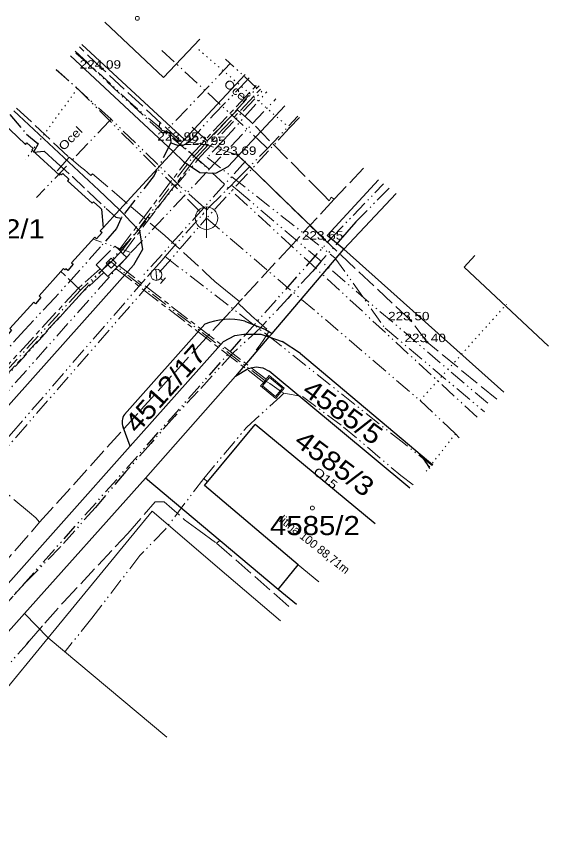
# Model space of a CAD drawing. Extents: x -683947 to -683762, y -1065756 to -1065543.
# Drawn here: x -683809.8 to -683762.4, y -1065615.3 to -1065542.6 of the extents above; entities that cross this region are included whole.
import ezdxf
from ezdxf.enums import TextEntityAlignment as Align

# ---------------------------------------------------------------- set-up
doc = ezdxf.new("R2010")
doc.units = 0
doc.header["$LTSCALE"] = 0.3
doc.header["$PDMODE"] = 32
doc.header["$PDSIZE"] = 0.15
for name, pattern in [('DASH_DOUBLE_DOT', [9.2, 5, -1.2, 0.3, -1.2, 0.3, -1.2]), ('DOTTED', [1.5, 0.3, -1.2]), ('LONG_DASH_SHORT_DASH', [9.9, 6, -1.2, 1.5, -1.2]), ('LONG_DASHED', [7.5, 6, -1.5])]:
    doc.linetypes.add(name, pattern=pattern)
for name, color, linetype, lineweight in [('1', 7, 'Continuous', 25), ('10', 7, 'Continuous', 13), ('25', 7, 'Continuous', 13), ('26', 7, 'LONG_DASH_SHORT_DASH', 13), ('3', 7, 'Continuous', 13), ('30', 7, 'LONG_DASHED', 13), ('31', 7, 'DASH_DOUBLE_DOT', 13), ('35', 7, 'LONG_DASHED', 13), ('36', 7, 'DASH_DOUBLE_DOT', 25), ('4', 7, 'Continuous', 13), ('41', 7, 'DASH_DOUBLE_DOT', 13), ('46', 7, 'DASH_DOUBLE_DOT', 13), ('5', 7, 'Continuous', 13), ('50', 7, 'LONG_DASHED', 13), ('51', 7, 'DOTTED', 13)]:
    doc.layers.add(name, color=color, linetype=linetype, lineweight=lineweight)
for name, color, linetype in [('16', 7, 'Continuous'), ('19', 7, 'Continuous'), ('2', 7, 'Continuous')]:
    doc.layers.add(name, color=color, linetype=linetype)

msp = doc.modelspace()

# ---------------------------------------------------------------- linework, layer by layer
at = {"layer": '1'}
for p, q in [((-683796.73, -1065548.04), (-683801.928, -1065543.107)), ((-683793.476, -1065544.62), (-683796.73, -1065548.04)), ((-683803.987, -1065545.115), (-683794.86, -1065553.55)), ((-683794.86, -1065553.55), (-683789.456, -1065547.788)), ((-683785.932, -1065550.565), (-683790.97, -1065555.96)), ((-683811.072, -1065552.024), (-683809.01, -1065554)), ((-683795.86, -1065554.64), (-683794.86, -1065553.55)), ((-683782.15, -1065562.09), (-683777.576, -1065557.148)), ((-683780.67, -1065563.32), (-683776.02, -1065558.374)), ((-683800.63, -1065559.83), (-683800.25, -1065560.2)), ((-683802.83, -1065562.26), (-683804.91, -1065564.54)), ((-683802.67, -1065562.4), (-683802.83, -1065562.26)), ((-683780.67, -1065563.32), (-683782.15, -1065562.09)), ((-683787.06, -1065570.81), (-683780.67, -1065563.32)), ((-683766.438, -1065576.048), (-683780.67, -1065563.32)), ((-683769.97, -1065564.92), (-683769.021, -1065563.888)), ((-683799.39, -1065564.75), (-683850.61, -1065622.17)), ((-683805.49, -1065565.16), (-683805.61, -1065565.05)), ((-683805.41, -1065565.07), (-683805.49, -1065565.16)), ((-683805.23, -1065565.23), (-683805.41, -1065565.07)), ((-683762.438, -1065571.952), (-683769.97, -1065564.92)), ((-683793.05, -1065570), (-683800.2, -1065578.03)), ((-683789.48, -1065569.72), (-683787.65, -1065570.48)), ((-683790.37, -1065571.01), (-683789.58, -1065570.87)), ((-683789.58, -1065570.87), (-683788.05, -1065570.87)), ((-683788.05, -1065570.87), (-683787.33, -1065571.13)), ((-683787.65, -1065570.48), (-683787.06, -1065570.81)), ((-683787.33, -1065571.13), (-683787.06, -1065570.81)), ((-683799.69, -1065580.85), (-683791.39, -1065571.52)), ((-683791.39, -1065571.52), (-683790.37, -1065571.01)), ((-683787.33, -1065571.13), (-683790.32, -1065574.63)), ((-683787.33, -1065571.13), (-683786.17, -1065571.54)), ((-683784.52, -1065572.61), (-683786.17, -1065571.54)), ((-683784.52, -1065572.61), (-683774.26, -1065581.22)), ((-683789.19, -1065573.93), (-683788.48, -1065573.79)), ((-683788.48, -1065573.79), (-683787.87, -1065573.87)), ((-683787.87, -1065573.87), (-683787.3, -1065574.18)), ((-683790.32, -1065574.63), (-683789.19, -1065573.93)), ((-683774.788, -1065584.598), (-683787.3, -1065574.18)), ((-683798.31, -1065583.7), (-683790.32, -1065574.63)), ((-683793.07, -1065584.35), (-683788.55, -1065578.91)), ((-683777.88, -1065587.764), (-683788.55, -1065578.91)), ((-683799.69, -1065580.85), (-683800.32, -1065579.15)), ((-683844.35, -1065631.04), (-683799.69, -1065580.85)), ((-683774.26, -1065581.22), (-683772.74, -1065582.501)), ((-683798.31, -1065583.7), (-683809.1, -1065595.75)), ((-683786.5, -1065593.59), (-683798.31, -1065583.7)), ((-683784.73, -1065591.4), (-683793.07, -1065584.35)), ((-683786.5, -1065593.59), (-683784.73, -1065591.4)), ((-683784.888, -1065594.94), (-683786.5, -1065593.59)), ((-683809.1, -1065595.75), (-683842.21, -1065632.76))]:
    msp.add_line(p, q, dxfattribs=at)
for points in [[(-683809.01, -1065554), (-683808.87, -1065553.86), (-683808.32, -1065554.37), (-683808.43, -1065554.49)], [(-683808.43, -1065554.49), (-683805.98, -1065556.74), (-683805.88, -1065556.63), (-683805.8, -1065556.71), (-683805.68, -1065556.58), (-683805.13, -1065557.09), (-683805.26, -1065557.23), (-683803.07, -1065559.24), (-683802.94, -1065559.1), (-683802.38, -1065559.61), (-683802.24, -1065559.77), (-683802.09, -1065561.42), (-683802.35, -1065561.7), (-683802.18, -1065561.85), (-683802.67, -1065562.4)], [(-683795.86, -1065554.64), (-683800.63, -1065559.83), (-683802.09, -1065561.42)], [(-683795.86, -1065554.64), (-683794.95, -1065555.51), (-683793.49, -1065556.51), (-683792.07, -1065556.55), (-683790.97, -1065555.96)], [(-683800.25, -1065560.2), (-683799.65, -1065560.85), (-683798.86, -1065561.69)], [(-683798.86, -1065561.69), (-683798.6, -1065563.36), (-683799.39, -1065564.75)], [(-683805.61, -1065565.05), (-683807.78, -1065567.47), (-683807.63, -1065567.62), (-683808.11, -1065568.17), (-683808.27, -1065568.02)], [(-683804.91, -1065564.54), (-683804.76, -1065564.66), (-683805.23, -1065565.23)], [(-683808.27, -1065568.02), (-683810.39, -1065570.39), (-683810.24, -1065570.54), (-683810.72, -1065571.09), (-683810.9, -1065570.93)], [(-683774.26, -1065581.22), (-683774.14, -1065581.342), (-683774.023, -1065581.467), (-683773.91, -1065581.595), (-683773.799, -1065581.726), (-683773.692, -1065581.859), (-683773.587, -1065581.995), (-683773.487, -1065582.133), (-683773.389, -1065582.274), (-683773.295, -1065582.416), (-683773.204, -1065582.562), (-683773.117, -1065582.709), (-683773.053, -1065582.822)]]:
    msp.add_lwpolyline(points, dxfattribs=at)
for centre, radius, start, end in [((-683790.831, -1065575.396), 5.835, 76.6146, 112.35461), ((-683799.206, -1065578.703), 1.201, 145.91206, 201.85693)]:
    msp.add_arc(centre, radius, start, end, dxfattribs=at)
for p in [(-683802.17, -1065547.26), (-683794.85, -1065553.57), (-683795.26, -1065553.67), (-683792.85, -1065554.05), (-683790.12, -1065554.93), (-683782.39, -1065562.47), (-683774.72, -1065569.65), (-683773.26, -1065571.59)]:
    msp.add_point(p, dxfattribs=at)
at = {"layer": '10'}
for p, q in [((-683792.885, -1065559.565), (-683792.885, -1065562.313)), ((-683797.393, -1065565.093), (-683797.323, -1065566.091)), ((-683796.524, -1065565.855), (-683796.982, -1065566.383)), ((-683796.98, -1065565.923), (-683796.753, -1065566.12))]:
    msp.add_line(p, q, dxfattribs=at)
for centre, radius in [((-683792.885, -1065560.567), 1), ((-683797.358, -1065565.594), 0.5)]:
    msp.add_circle(centre, radius, dxfattribs=at)
at = {"layer": '25'}
for p, q in [((-683790.099, -1065554.894), (-683790.145, -1065554.94)), ((-683790.095, -1065554.948), (-683782.367, -1065562.451))]:
    msp.add_line(p, q, dxfattribs=at)
at = {"layer": '26'}
for p, q in [((-683800.96, -1065565.04), (-683787.8, -1065575.17)), ((-683800.7, -1065564.78), (-683787.57, -1065574.9))]:
    msp.add_line(p, q, dxfattribs=at)
for points in [[(-683800.67, -1065563.39), (-683794.31, -1065555), (-683788.371, -1065548.643)], [(-683800.35, -1065563.72), (-683793.93, -1065555.32), (-683787.98, -1065548.95)], [(-683802.34, -1065565.06), (-683804.28, -1065566.78), (-683816.53, -1065580.13), (-683823.89, -1065588.24), (-683833.6, -1065599.23)], [(-683802.02, -1065565.39), (-683803.92, -1065567.14), (-683816.16, -1065580.47), (-683823.51, -1065588.58), (-683833.25, -1065599.54)]]:
    msp.add_lwpolyline(points, dxfattribs=at)
for points in [[(-683802.7, -1065564.71), (-683801.03, -1065563.04), (-683800.67, -1065563.39), (-683800.35, -1065563.72), (-683799.99, -1065564.07), (-683800.7, -1065564.78), (-683800.96, -1065565.04), (-683801.66, -1065565.74), (-683802.02, -1065565.39), (-683802.34, -1065565.06)], [(-683801.82, -1065564.57), (-683801.38, -1065564.13), (-683800.94, -1065564.57), (-683801.38, -1065565.01)], [(-683788.07, -1065575.49), (-683787.8, -1065575.17), (-683787.57, -1065574.9), (-683787.3, -1065574.57), (-683785.97, -1065575.69), (-683786.23, -1065576.01), (-683786.47, -1065576.29), (-683786.73, -1065576.61)], [(-683787.9, -1065575.48), (-683787.29, -1065574.74), (-683786.13, -1065575.7), (-683786.75, -1065576.44)]]:
    msp.add_lwpolyline(points, close=True, dxfattribs=at)
at = {"layer": '30'}
for points in [[(-683790.12, -1065554.93), (-683792.85, -1065554.05), (-683795.26, -1065553.67), (-683802.17, -1065547.26), (-683804.196, -1065545.319)], [(-683767.054, -1065576.678), (-683773.26, -1065571.59), (-683774.72, -1065569.65), (-683782.39, -1065562.47), (-683790.12, -1065554.93)]]:
    msp.add_lwpolyline(points, dxfattribs=at)
at = {"layer": '31'}
for p, q in [((-683788.4, -1065548.98), (-683791.191, -1065546.421)), ((-683788.4, -1065548.98), (-683788.205, -1065548.773)), ((-683791.34, -1065553.6), (-683787.516, -1065549.316)), ((-683799.62, -1065563.63), (-683802.97, -1065562.42)), ((-683776.99, -1065570.36), (-683768.144, -1065577.794)), ((-683786, -1065576.14), (-683786.22, -1065576)), ((-683793.13, -1065583.71), (-683792.8, -1065584.01))]:
    msp.add_line(p, q, dxfattribs=at)
for points in [[(-683792.64, -1065556.2), (-683799.41, -1065550.51), (-683804.577, -1065545.69)], [(-683844.16, -1065612.25), (-683839.52, -1065607), (-683832.27, -1065598.52), (-683799.27, -1065561.98), (-683793.42, -1065555.08), (-683787.795, -1065549.096)], [(-683801.38, -1065564.44), (-683800.5, -1065563.57), (-683794.12, -1065555.16), (-683788.4, -1065548.98)], [(-683799.62, -1065563.63), (-683792.64, -1065556.2), (-683786.719, -1065549.944)], [(-683791.34, -1065553.6), (-683792.82, -1065555.16), (-683781.46, -1065564.09), (-683776.99, -1065570.36)], [(-683841.77, -1065605.48), (-683839.42, -1065608.5), (-683799.62, -1065563.63)], [(-683801.38, -1065564.44), (-683804.1, -1065566.96), (-683816.34, -1065580.3), (-683823.7, -1065588.41)], [(-683786.22, -1065576), (-683787.26, -1065575.28), (-683787.68, -1065575.03), (-683800.84, -1065564.91), (-683801.38, -1065564.44)], [(-683804.1, -1065566.96), (-683805.53, -1065565.6), (-683805.84, -1065565.31)], [(-683793.13, -1065583.71), (-683789.3, -1065579.15), (-683786.34, -1065576.47), (-683786, -1065576.14)], [(-683786, -1065576.14), (-683784.35, -1065576.43), (-683780.69, -1065579.15), (-683775.58, -1065583.47), (-683774.482, -1065584.284)], [(-683793.13, -1065583.71), (-683796.54, -1065588.22), (-683798.81, -1065590.57), (-683803.09, -1065596.16), (-683805.48, -1065599.12)]]:
    msp.add_lwpolyline(points, dxfattribs=at)
at = {"layer": '35'}
for p, q in [((-683791.086, -1065558.025), (-683790.672, -1065557.612)), ((-683791.987, -1065589.477), (-683791.739, -1065589.28)), ((-683791.987, -1065589.477), (-683785.281, -1065595.342))]:
    msp.add_line(p, q, dxfattribs=at)
for points in [[(-683809.787, -1065550.771), (-683805.12, -1065555.14), (-683804.1, -1065555.98), (-683803.75, -1065556.26), (-683803.48, -1065556.51)], [(-683778.905, -1065556.101), (-683781.53, -1065558.87), (-683785.235, -1065562.893), (-683789.699, -1065567.708), (-683789.948, -1065567.987), (-683790.074, -1065568.129)], [(-683803.48, -1065556.51), (-683803.19, -1065556.77), (-683803.03, -1065556.62), (-683796.6, -1065562.1), (-683792.978, -1065565.422), (-683792.14, -1065566.19), (-683791.185, -1065566.973), (-683789.948, -1065567.987)], [(-683790.672, -1065557.612), (-683790.402, -1065557.337), (-683790.126, -1065557.059)], [(-683790.672, -1065557.612), (-683790.454, -1065557.792), (-683790.158, -1065558.044)], [(-683896.24, -1065687.55), (-683894.71, -1065685.72), (-683893.48, -1065684.13), (-683891.61, -1065681.955), (-683887.89, -1065677.63), (-683886.16, -1065675.53), (-683853.44, -1065639.1), (-683848.45, -1065633.59), (-683843.114, -1065627.22), (-683843.08, -1065627.18), (-683831.4, -1065614.21), (-683820.06, -1065601.41), (-683812.91, -1065593.55), (-683807.75, -1065587.62), (-683793.84, -1065572.21), (-683791.969, -1065570.179), (-683790.708, -1065568.809), (-683790.074, -1065568.129)], [(-683790.074, -1065568.129), (-683788.87, -1065569.24), (-683787.32, -1065570.62), (-683787.85, -1065571.46), (-683788.04, -1065571.73), (-683788.47, -1065572.31)], [(-683808.67, -1065598.185), (-683807.29, -1065596.593), (-683805.621, -1065594.724), (-683799.904, -1065588.627), (-683797.444, -1065585.805), (-683796.652, -1065585.795)], [(-683796.652, -1065585.795), (-683794.833, -1065587.39), (-683793.539, -1065588.345), (-683791.987, -1065589.477)]]:
    msp.add_lwpolyline(points, dxfattribs=at)
at = {"layer": '36'}
for p, q in [((-683796.15, -1065552.96), (-683796.05, -1065553.86)), ((-683776.644, -1065557.882), (-683779.59, -1065560.9)), ((-683779.59, -1065560.9), (-683780.391, -1065561.807))]:
    msp.add_line(p, q, dxfattribs=at)
at = {"layer": '36', "lineweight": 13}
for p, q in [((-683789.43, -1065555.5), (-683798.629, -1065565.77)), ((-683790.158, -1065558.044), (-683767.603, -1065577.241)), ((-683796.578, -1065563.976), (-683792.872, -1065559.824)), ((-683796.84, -1065564.29), (-683796.578, -1065563.976)), ((-683796.27, -1065564.22), (-683796.578, -1065563.976))]:
    msp.add_line(p, q, dxfattribs=at)
at = {"layer": '36'}
for points in [[(-683796.15, -1065552.96), (-683796.82, -1065552.97), (-683798.58, -1065551.35), (-683800.66, -1065549.45), (-683803.39, -1065546.85), (-683804.656, -1065545.768)], [(-683796.05, -1065553.86), (-683795.46, -1065554.07), (-683794.97, -1065554.08), (-683794.39, -1065553.76), (-683792.25, -1065551.34), (-683789.87, -1065548.91), (-683789.101, -1065548.068)], [(-683810.38, -1065551.349), (-683808.92, -1065553.09), (-683807.88, -1065553.96), (-683808.28, -1065554.7)], [(-683796.15, -1065552.96), (-683796.84, -1065552.77), (-683797.1, -1065552.45), (-683797.01, -1065552.04)], [(-683796.05, -1065553.86), (-683797.56, -1065556.77), (-683800.49, -1065560.55)], [(-683808.28, -1065554.7), (-683807.34, -1065554.61), (-683806.23, -1065555.6), (-683804.83, -1065556.86), (-683803.35, -1065558.25), (-683801.83, -1065559.69), (-683800.97, -1065560.48), (-683800.49, -1065560.55)], [(-683800.49, -1065560.55), (-683800.89, -1065561.47), (-683802.33, -1065563.11), (-683804.19, -1065565.23), (-683806.4, -1065567.64), (-683809.07, -1065570.49), (-683811.9, -1065573.65), (-683813.94, -1065576.12), (-683815.51, -1065577.95)], [(-683780.391, -1065561.807), (-683782.7, -1065564.42), (-683783.44, -1065565.28), (-683785.65, -1065567.7), (-683788.09, -1065570.32), (-683790.52, -1065572.55), (-683793.62, -1065575.94), (-683795.75, -1065578.2), (-683797.85, -1065580.61), (-683800.07, -1065583.11), (-683802.78, -1065586.29), (-683805.93, -1065589.86), (-683808.99, -1065592.97), (-683812.14, -1065596.4), (-683814.68, -1065599.44), (-683817.17, -1065602.3), (-683820.49, -1065605.87), (-683823.62, -1065609.31), (-683825.7, -1065611.73), (-683828.07, -1065614.55), (-683831.17, -1065618.13)], [(-683816.844, -1065611.315), (-683817.806, -1065610.911), (-683818.52, -1065610.227), (-683818.714, -1065609.734), (-683818.377, -1065609.192), (-683817.615, -1065607.976), (-683815.022, -1065605.096), (-683812.85, -1065602.939), (-683811.5, -1065601.448), (-683808.88, -1065598.46), (-683808.67, -1065598.185)]]:
    msp.add_lwpolyline(points, dxfattribs=at)
at = {"layer": '36', "lineweight": 13}
for points in [[(-683795.228, -1065557.729), (-683801.38, -1065551.757), (-683806.265, -1065547.336)], [(-683790.126, -1065557.059), (-683787.448, -1065554.367), (-683784.757, -1065551.49)], [(-683792.872, -1065559.824), (-683793.348, -1065559.395), (-683795.228, -1065557.729)], [(-683792.872, -1065559.824), (-683792.66, -1065559.596), (-683791.086, -1065558.025)], [(-683853.405, -1065628.437), (-683847.424, -1065621.75), (-683837.692, -1065610.319), (-683826.563, -1065598.101), (-683821.765, -1065592.734), (-683810.241, -1065579.722), (-683798.152, -1065565.762), (-683797.335, -1065564.872), (-683796.84, -1065564.29)], [(-683772.814, -1065582.577), (-683775.342, -1065580.59), (-683786.55, -1065571.679), (-683796.27, -1065564.22)]]:
    msp.add_lwpolyline(points, dxfattribs=at)
at = {"layer": '4'}
for p, q in [((-683805.006, -1065546.109), (-683795.86, -1065554.64)), ((-683802.48, -1065558.07), (-683810.031, -1065551.009)), ((-683802.48, -1065558.07), (-683800.63, -1065559.83)), ((-683806.98, -1065597.89), (-683797.73, -1065586.62)), ((-683797.73, -1065586.62), (-683791.1, -1065592.29)), ((-683784.73, -1065591.4), (-683782.9, -1065592.904)), ((-683791.1, -1065592.29), (-683786.304, -1065596.39)), ((-683809.1, -1065595.75), (-683806.98, -1065597.89)), ((-683817.57, -1065610.69), (-683806.98, -1065597.89)), ((-683796.424, -1065606.751), (-683806.98, -1065597.89))]:
    msp.add_line(p, q, dxfattribs=at)
at = {"layer": '41'}
for p, q in [((-683790.74, -1065546.776), (-683796.47, -1065552.759)), ((-683796.47, -1065552.759), (-683768.698, -1065578.362))]:
    msp.add_line(p, q, dxfattribs=at)
at = {"layer": '41', "lineweight": 25}
msp.add_lwpolyline([(-683907.26, -1065705.67), (-683893.37, -1065687.98), (-683887.71, -1065681.96), (-683876.81, -1065669.67), (-683869.01, -1065660.17), (-683861.43, -1065651.54), (-683852.89, -1065642.04), (-683845.02, -1065633.03), (-683836.31, -1065623.45), (-683820.34, -1065605.7), (-683789.54, -1065571.05), (-683781.76, -1065562.31), (-683777.124, -1065557.504)], dxfattribs=at)
at = {"layer": '46'}
for points in [[(-683806.282, -1065547.353), (-683804.37, -1065549.013), (-683792.885, -1065560.567)], [(-683784.617, -1065551.6), (-683785.49, -1065552.529), (-683792.885, -1065560.567)], [(-683826.197, -1065598.918), (-683819.004, -1065590.616), (-683809.84, -1065580.04), (-683792.885, -1065560.567)], [(-683792.885, -1065560.567), (-683773.884, -1065576.785), (-683770.73, -1065579.748), (-683770.391, -1065580.095)]]:
    msp.add_lwpolyline(points, dxfattribs=at)
at = {"layer": '5'}
for centre in [(-683799.047, -1065542.779), (-683783.467, -1065586.349)]:
    msp.add_circle(centre, 0.175, dxfattribs=at)
at = {"layer": '50'}
for points in [[(-683781.53, -1065558.87), (-683781.8, -1065558.69), (-683781.97, -1065559.02), (-683782.519, -1065558.465), (-683789.02, -1065551.9), (-683790.13, -1065550.92), (-683790.338, -1065551.132), (-683792.84, -1065553.67), (-683794.189, -1065552.441)], [(-683806.178, -1065556.338), (-683805.883, -1065556.011), (-683805.12, -1065555.14)], [(-683807.75, -1065587.62), (-683808.08, -1065587.23), (-683808.653, -1065586.748), (-683814.89, -1065581.51), (-683818.084, -1065578.857)]]:
    msp.add_lwpolyline(points, dxfattribs=at)
at = {"layer": '51'}
for p, q in [((-683785.49, -1065552.529), (-683793.747, -1065545.425)), ((-683804.37, -1065549.013), (-683808.973, -1065555.351)), ((-683773.884, -1065576.785), (-683766.18, -1065568.213)), ((-683770.73, -1065579.748), (-683773.534, -1065583.314))]:
    msp.add_line(p, q, dxfattribs=at)
at = {"layer": '51', "linetype": 'DASH_DOUBLE_DOT'}
for points in [[(-683787.448, -1065554.367), (-683787.596, -1065554.209), (-683797.098, -1065545.419)], [(-683801.38, -1065551.757), (-683801.526, -1065551.906), (-683808.025, -1065558.729)]]:
    msp.add_lwpolyline(points, dxfattribs=at)

# ---------------------------------------------------------------- texts
at = {"layer": '16', "width": 1.25}
msp.add_text('O15', height=0.75, rotation=321.84, dxfattribs=at).set_placement((-683783.455, -1065583.258))
at = {"layer": '16'}
msp.add_text('litina 100 88,71m', height=0.75, rotation=321.51, dxfattribs=at).set_placement((-683786.501, -1065587.514))
at = {"layer": '19', "width": 1.2}
for rotation, p in [(319.38, (-683791.417, -1065548.709)), (45.01, (-683805.602, -1065554.607))]:
    msp.add_text('Ocel ', height=0.75, rotation=rotation, dxfattribs=at).set_placement(p)
at = {"layer": '2', "width": 1.15}
msp.add_text('2402/1', height=1.7, dxfattribs=at).set_placement((-683811.27, -1065562.36), align=Align.CENTER)
for s, rotation, p in [('4512/17', 48.338, (-683795.918, -1065576.271)), ('4585/5', 324.072, (-683781.248, -1065578.488))]:
    msp.add_text(s, height=1.7, rotation=rotation, dxfattribs=at).set_placement(p, align=Align.CENTER)
msp.add_text('4585/3', height=1.7, rotation=323.13, dxfattribs=at).set_placement((-683785.2, -1065580.65))
msp.add_text('4585/2', height=1.7, dxfattribs=at).set_placement((-683787.24, -1065588.76))
at = {"layer": '3', "width": 1.2}
for s, p in [('224 09 ', (-683802.17, -1065547.26)), ('223 95 ', (-683795.26, -1065553.67)), ('223 95 ', (-683792.85, -1065554.05)), ('223 69 ', (-683790.12, -1065554.93)), ('223 65 ', (-683782.39, -1065562.47)), ('223 50 ', (-683774.72, -1065569.65)), ('223 40 ', (-683773.26, -1065571.59))]:
    msp.add_text(s, height=0.75, dxfattribs=at).set_placement(p, align=Align.CENTER)

doc.saveas('drawing.dxf')
